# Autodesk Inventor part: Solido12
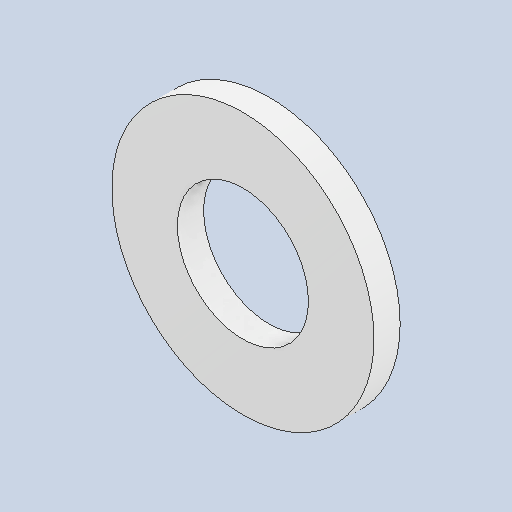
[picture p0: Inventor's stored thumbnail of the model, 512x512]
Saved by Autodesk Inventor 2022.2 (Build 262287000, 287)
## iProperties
Created: 2024-10
Part Number: Solido12
Material: Generico
Document SubType Name: Modeling
Designer: 18907419
Density: 1 g/cm^3
Appearance: Default
Author: 18907419
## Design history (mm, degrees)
feature "Solido12"
node "Solido1"
